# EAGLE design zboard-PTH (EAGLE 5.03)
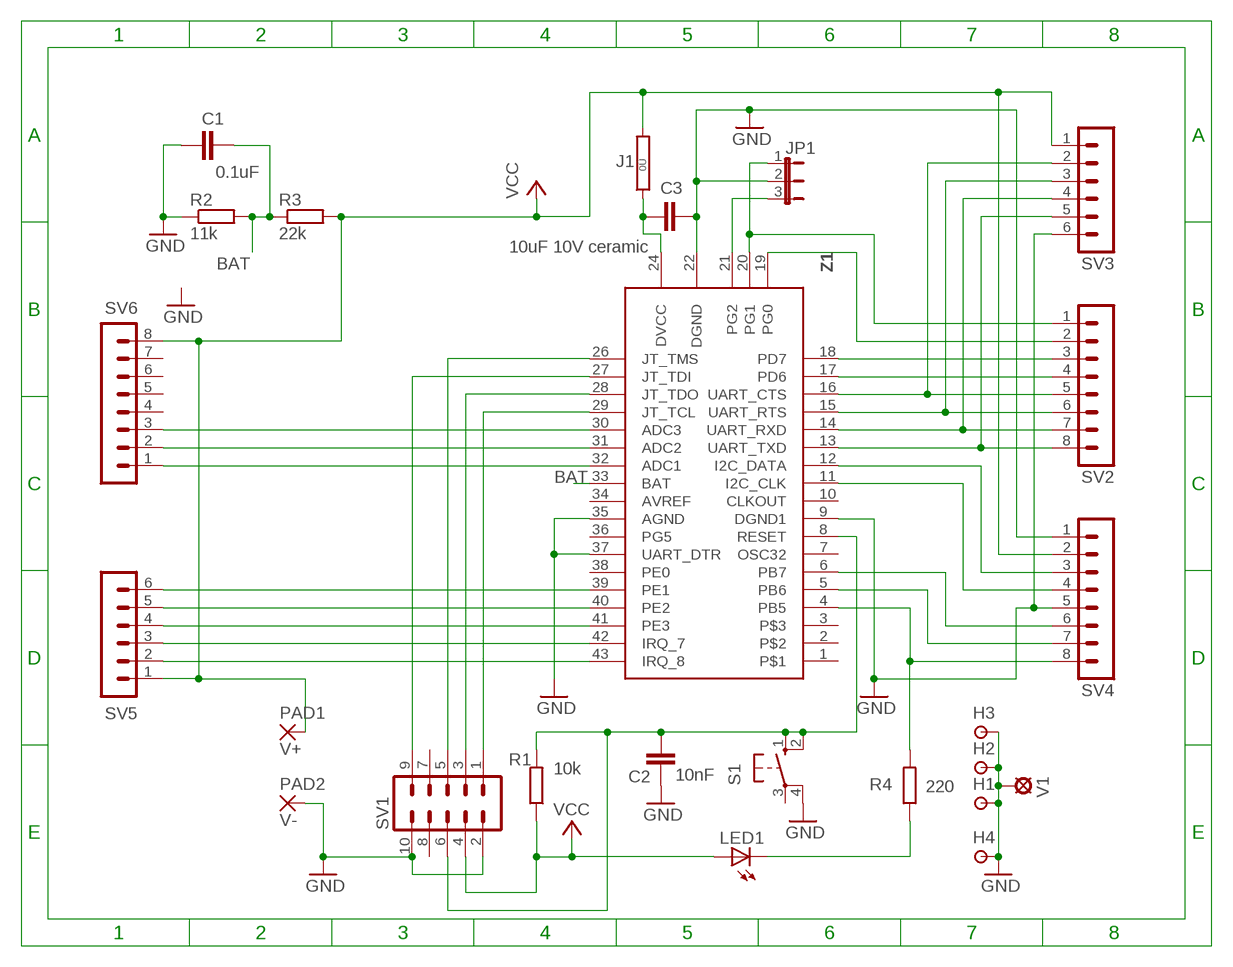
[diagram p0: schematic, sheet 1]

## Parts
C1  0.1uF  C5P  [C050-030-075]
C2  10nF  C5P  [C050-030-075]
C3  10uF 10V ceramic  CSMT0805  [C0805]
H1  HOLE/SMALL  [1,6/0,8]
H2  HOLE/SMALL  [1,6/0,8]
H3  HOLE/SMALL  [1,6/0,8]
H4  HOLE/SMALL  [1,6/0,8]
J1  0R  [0R/10]
JP1  JP2E  [JP2]
LED1  LED-3MM3MM  [HLMP-D105]
PAD1  V+  TERMINAL-PAD  [2,54/1,1]
PAD2  V-  TERMINAL-PAD  [2,54/1,1]
R1  10k  R  [0207/10]
R2  11k  R  [0207/10]
R3  22k  R  [0207/10]
R4  220  R  [0207/10]
S1  10-XX  [B3F-10XX]
SV1  ML10  [ML10]
SV2  MA08-1  [MA08-1]
SV3  MA06-1  [MA06-1]
SV4  MA08-1  [MA08-1]
SV5  MA06-1  [MA06-1]
SV6  MA08-1  [MA08-1]
V1  HOLE/VIA  [LSP10]
Z1  ZDM-A1281-A2N  [ZIGSMD]

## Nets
BAT: C1.2 R2.2 R3.1 Z1.33(BAT)
GND: C1.1 C2.1 C3.2 H1.1(P) H2.1(P) H3.1(P) H4.1(P) JP1.2 PAD2.1(P) R2.1 S1.4(P1) SV1.2 SV1.10 SV3.6 SV4.1 SV4.5 V1.MP Z1.9(DGND1) Z1.22(DGND) Z1.35(AGND) Z1.37(UART_DTR)
N$3: SV6.2 Z1.31(ADC2)
N$4: SV6.3 Z1.30(ADC3)
N$5: SV6.1 Z1.32(ADC1)
N$7: SV5.4 Z1.41(PE3)
N$9: SV1.5 Z1.26(JT_TMS)
N$10: SV1.1 Z1.29(JT_TCL)
N$11: SV1.3 Z1.28(JT_TDO)
N$12: SV5.6 Z1.39(PE1)
N$13: C2.2 R1.2 S1.1(S) S1.2(S1) SV1.6 Z1.8(RESET)
N$14: SV5.3 Z1.42(IRQ_7)
N$15: SV5.2 Z1.43(IRQ_8)
N$16: SV2.3 Z1.18(PD7)
N$17: SV2.4 Z1.17(PD6)
N$18: SV2.5 SV3.2 Z1.16(UART_CTS)
N$19: SV2.6 SV3.3 Z1.15(UART_RTS)
N$20: SV2.7 SV3.4 Z1.14(UART_RXD)
N$21: SV2.8 SV3.5 Z1.13(UART_TXD)
N$22: SV4.3 Z1.12(I2C_DATA)
N$23: SV4.4 Z1.11(I2C_CLK)
N$24: SV2.2 Z1.19(PG0)
N$25: JP1.1 SV2.1 Z1.20(PG1)
N$26: SV4.6 Z1.6(PB7)
N$27: SV4.7 Z1.5(PB6)
N$28: R4.2 SV4.8 Z1.4(PB5)
N$29: JP1.3 Z1.21(PG2)
N$30: LED1.K(C) R4.1
N$31: SV1.9 Z1.27(JT_TDI)
N$32: SV5.5 Z1.40(PE2)
N$33 [supply]: C3.1 J1.1 Z1.24(DVCC)
VCC: J1.2 LED1.A PAD1.1(P) R1.1 R3.2 SV1.4 SV3.1 SV4.2 SV5.1 SV6.8
Unconnected: S1.3(P) SV1.7 SV1.8 SV6.4 SV6.5 SV6.6 SV6.7 Z1.1 Z1.2 Z1.3 Z1.7(OSC32) Z1.10(CLKOUT) Z1.34(AVREF) Z1.36(PG5) Z1.38(PE0)

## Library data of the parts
C1-C3 = ee2parts:C: Capacitor
H1-H4 = ee2parts:HOLE/SMALL: SMALL THROUGH-HOLE PAD/TESTPOINT
J1 = jumper:0R: Bridge 0R 10mm
JP1 = jumper:JP2E: JUMPER
LED1 = ee2parts:LED-3MM: LED
PAD1 PAD2 = ee2parts:TERMINAL-PAD: LARGE THROUGH-HOLE PAD
R1-R4 = ee2parts:R: Resistor
S1 = switch-omron:10-XX: OMRON SWITCH
SV1 = con-harting-ml:ML10: HARTING
SV2 SV4 SV6 = con-lstb:MA08-1: PIN HEADER
SV3 SV5 = con-lstb:MA06-1: PIN HEADER
V1 = ee2parts:HOLE/VIA: FIXED VIA
Z1 = ee2parts:ZDM-A1281-A2

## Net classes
1 supply: width 0.635 mm

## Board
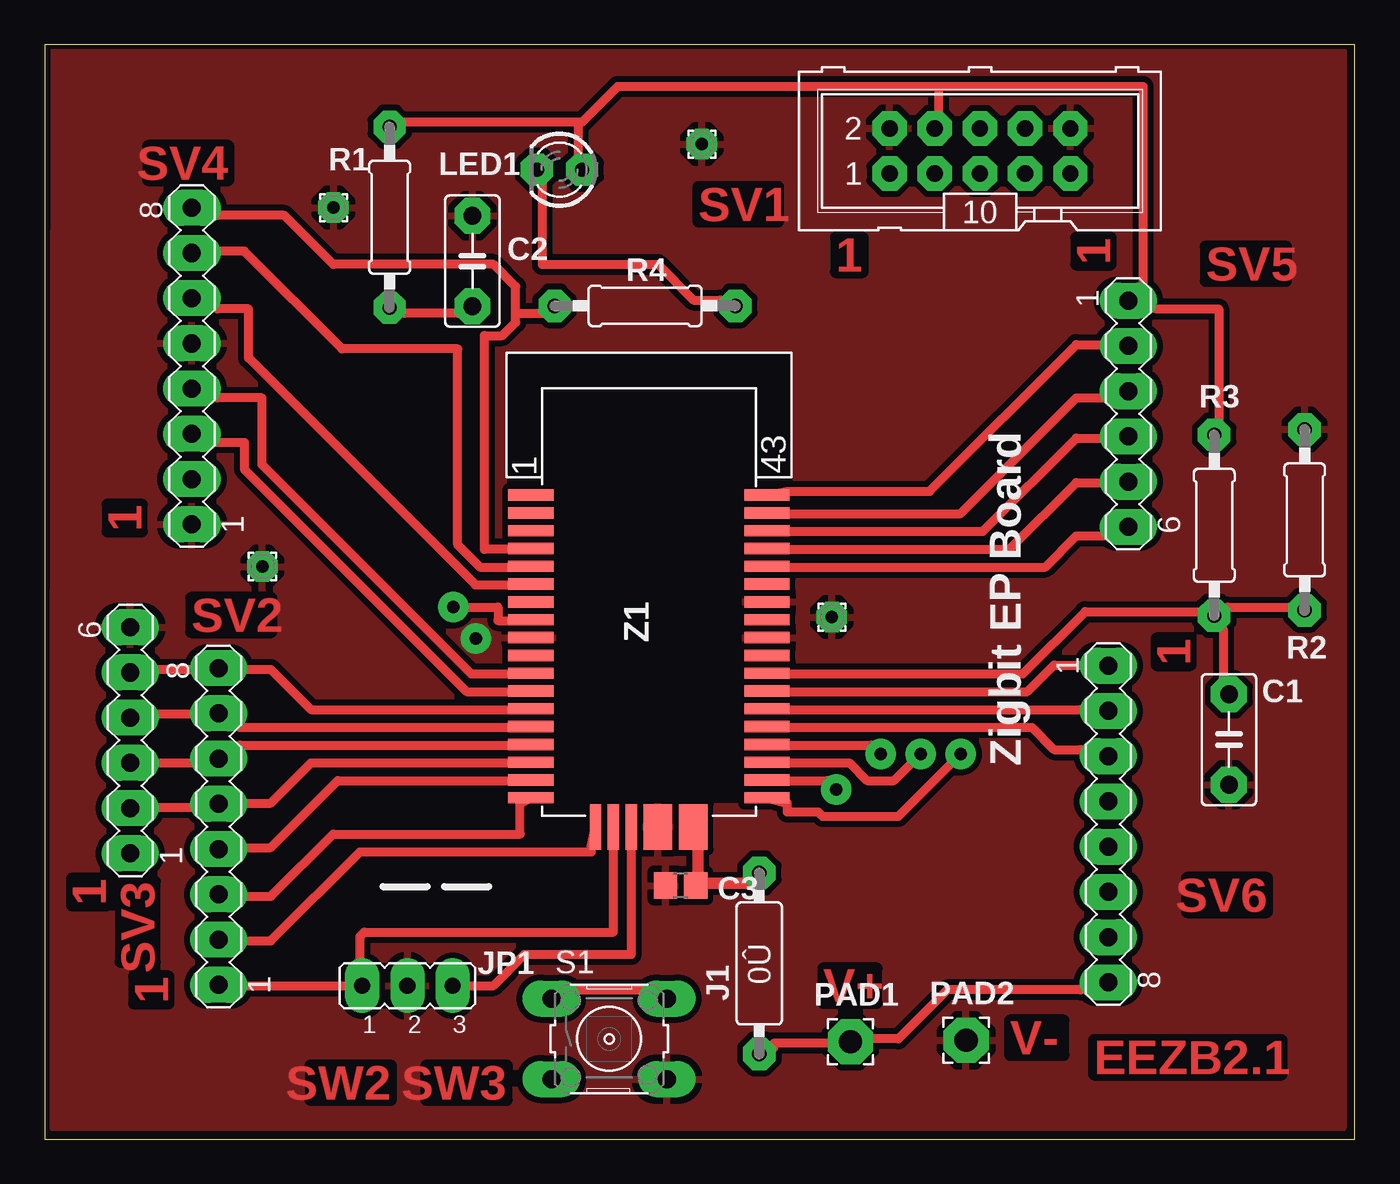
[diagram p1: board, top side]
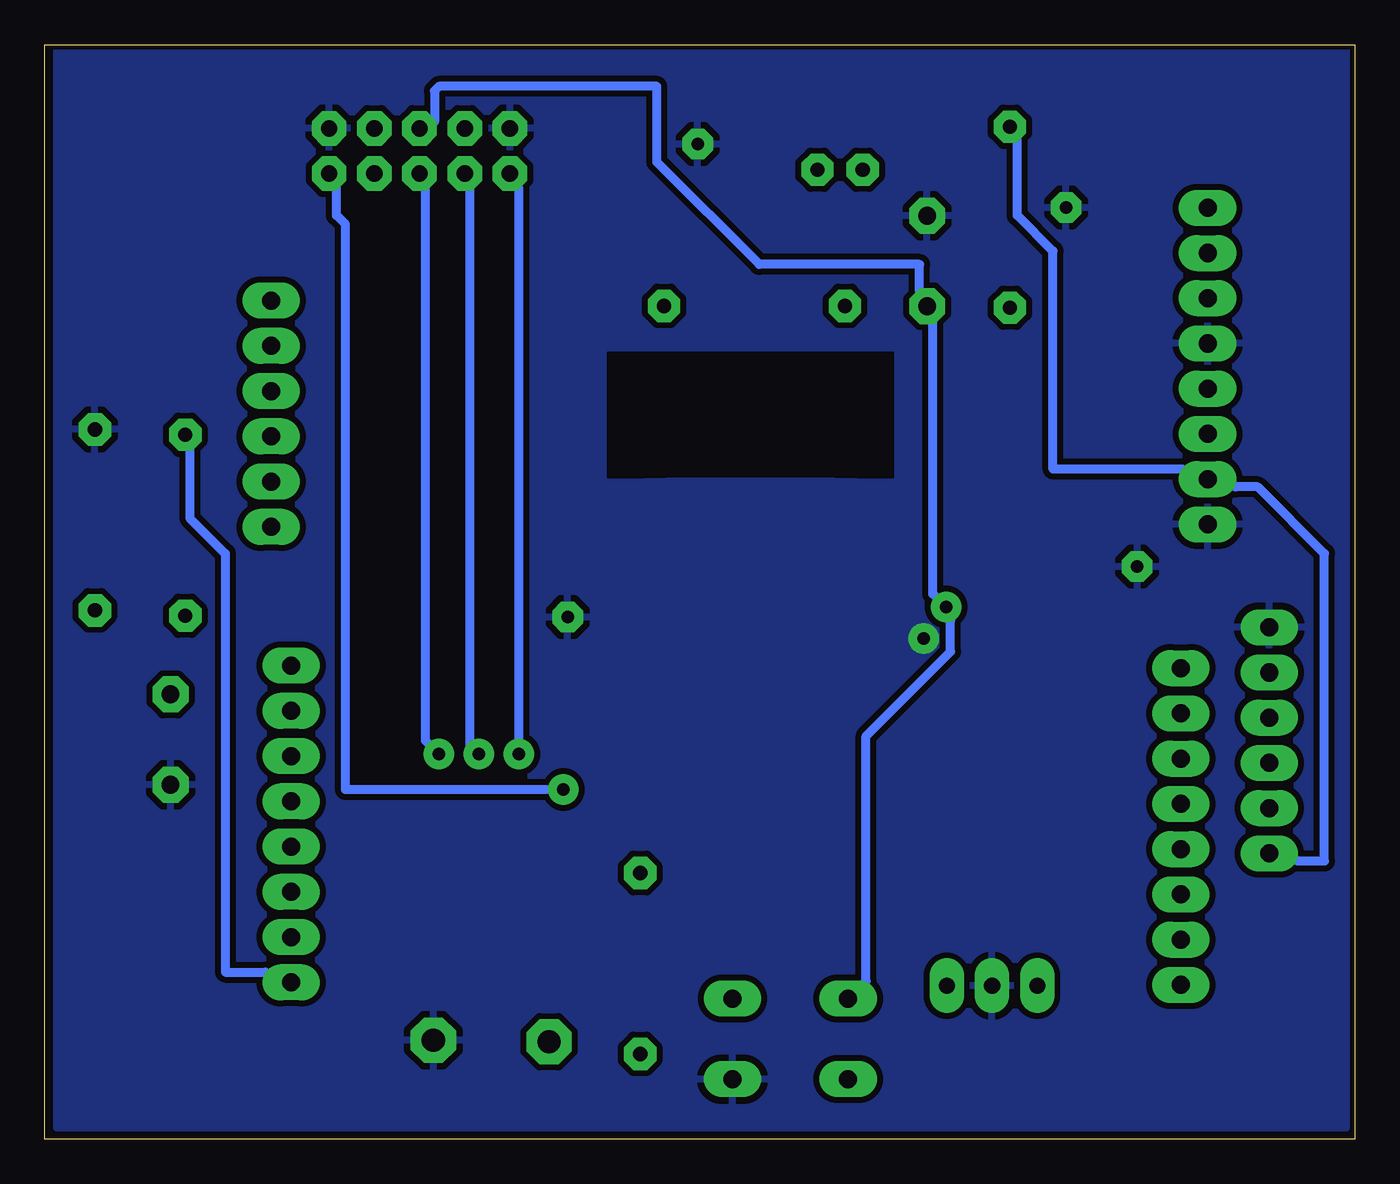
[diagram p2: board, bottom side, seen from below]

Size 73.63 x 61.48 mm. Coordinates in mm from the lower left corner, seen from the top.
Outline: 0,0 73.63,0 73.63,61.48 0,61.48 0,0
Copper layers (1*16): Top 0.035mm / dielectric 1.5mm / Bottom 0.035mm
Design rules "zigbit_rules *": minimum track width 20mil, minimum drill 0.7mm, track to track 13mil, track to pad 13mil, pad to pad 13mil, via to via 13mil, smd to smd 0mil, copper to edge 10mil, drill to drill 10mil, minimum pad ring 20mil, minimum via ring 20mil, stop-mask expansion 0mil, vias tented up to drill 0mil, thermal gap 15mil

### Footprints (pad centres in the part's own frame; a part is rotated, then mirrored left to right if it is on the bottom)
C050-030-075 = drill 1 octagon: 1 -2.54,0; 2 2.54,0
C0805 = smd 1.3 x 1.5: 1 -0.85,0; 2 0.85,0
1,6/0,8 = drill 0.7 pad 1.6 octagon: 1 0,0
0R/10 = drill 0.813 pad 1.6 octagon: 1 -5.08,0; 2 5.08,0
JP2 = drill 0.914 long: 1 -2.54,0; 2 0,0; 3 2.54,0
HLMP-D105 = drill 0.8 octagon: A -1.27,0; K 1.27,0
2,54/1,1 = drill 1.3 pad 2.54 octagon: 1 0,0
0207/10 = drill 0.8 octagon: 1 -5.08,0; 2 5.08,0
B3F-10XX = drill 1.016 long: 1 -3.251,2.261; 2 3.251,2.261; 3 -3.251,-2.261; 4 3.251,-2.261
ML10 = drill 0.914 octagon: 1 -5.08,-1.27; 2 -5.08,1.27; 3 -2.54,-1.27; 4 -2.54,1.27; 5 0,-1.27; 6 0,1.27; 7 2.54,-1.27; 8 2.54,1.27; 9 5.08,-1.27; 10 5.08,1.27
MA08-1 = drill 1.016 long: 1 -8.89,0; 2 -6.35,0; 3 -3.81,0; 4 -1.27,0; 5 1.27,0; 6 3.81,0; 7 6.35,0; 8 8.89,0
MA06-1 = drill 1.016 long: 1 -6.35,0; 2 -3.81,0; 3 -1.27,0; 4 1.27,0; 5 3.81,0; 6 6.35,0
LSP10 = drill 0.7 pad 1.016 round: MP 0,0
ZIGSMD = smd 0.635 x 2.54: 1 7,6.635; 2 6,6.635; 3 5,6.635; 4 4,6.635; 5 3,6.635; 6 2,6.635; 7 1,6.635; 8 0,6.635; 9 -1,6.635; 10 -2,6.635; 11 -3,6.635; 12 -4,6.635; 13 -5,6.635; 14 -6,6.635; 15 -7,6.635; 16 -8,6.635; 17 -9,6.635; 18 -10,6.635; 26 -10,-6.635; 27 -9,-6.635; 28 -8,-6.635; 29 -7,-6.635; 30 -6,-6.635; 31 -5,-6.635; 32 -4,-6.635; 33 -3,-6.635; 34 -2,-6.635; 35 -1,-6.635; 36 0,-6.635; 37 1,-6.635; 38 2,-6.635; 39 3,-6.635; 40 4,-6.635; 41 5,-6.635; 42 6,-6.635; 43 7,-6.635 | smd 2.54 x 0.635: 19 -11.635,3; 20 -11.635,2; 21 -11.635,1 | smd 2.54 x 1.6: 22 -11.635,-0.5; 24 -11.635,-2.5

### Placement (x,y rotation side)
C1  66.55,22.44 90 top
C2  24.04,49.32 270 top
C3  35.74,14.25 180 top
H1  44.24,29.32 0 top
H2  36.94,55.89 0 top
H3  12.24,32.16 0 top
H4  16.24,52.32 0 top
J1  40.16,9.87 270 top
JP1  20.39,8.62 0 top
LED1  28.93,54.45 180 top
PAD1  45.28,5.47 0 top
PAD2  51.78,5.55 0 top
R1  19.39,51.78 270 top
R2  70.8,34.78 270 top
R3  65.72,34.48 90 top
R4  33.74,46.8 180 top
S1  31.73,5.63 0 top
SV1  52.56,55.5 0 top
SV2  9.78,17.56 90 top
SV3  4.82,22.4 90 top
SV4  8.28,43.42 90 top
SV5  60.89,40.74 270 top
SV6  59.77,17.7 270 top
V1  24.24,28.13 0 top
Z1  33.96,29.17 90 top

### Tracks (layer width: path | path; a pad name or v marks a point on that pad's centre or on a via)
BAT
  Top 0.508: Z1.33 41.72,26.13 54.97,26.13 58.47,29.63 64.97,29.63 R3.1 | R2.2 69.97,29.88 66.47,29.88 R3.1 | C1.2 66.22,25.88 66.22,28.63 R3.1
GND
  pour Bottom: 0.47,61.13 72.97,61.13 72.97,0.63 0.47,0.63
  pour Top: 0.53,61.13 72.97,61.13 72.97,0.63 0.47,0.63
N$3
  Top 0.508: Z1.31 41.72,24.13 58.22,24.13 SV6.2
N$4
  Top 0.508: Z1.30 41.72,23.13 55.47,23.13 56.72,21.88 58.22,21.88 SV6.3
N$5
  Top 0.508: Z1.32 41.72,25.13 55.22,25.13 56.72,26.63 58.22,26.63 SV6.1
N$7
  Top 0.508: Z1.41 41.72,34.13 52.72,34.13 57.97,39.38 59.47,39.38 SV5.4
N$9  (via drill 0.7)
  Top 0.508: v51.47,21.63 47.97,18.13 43.72,18.13 43.47,18.38 41.72,18.38 41.72,18.88 Z1.26
  Bottom 0.508: v51.47,21.63 52.22,22.38 52.22,53.38 SV1.5
N$10  (via drill 0.7)
  Top 0.508: v46.97,21.63 46.47,22.13 41.72,22.13 Z1.29
  Bottom 0.508: v46.97,21.63 46.97,53.38 SV1.1
N$11  (via drill 0.7)
  Top 0.508: v49.22,21.63 47.72,20.13 46.22,20.13 45.22,21.13 41.72,21.13 Z1.28
  Bottom 0.508: v49.22,21.63 49.72,22.13 49.72,53.38 SV1.3
N$12
  Top 0.508: Z1.39 41.72,32.13 56.22,32.13 57.97,33.88 59.47,33.88 SV5.6
N$13  (via drill 0.7)
  Top 0.508: S1.1 29.97,8.38 33.47,8.38 S1.2 | v22.97,29.88 25.47,29.88 25.47,29.13 26.22,29.13 Z1.8 | R1.2 20.22,46.38 23.22,46.38 C2.2
  Bottom 0.508: SV1.6 51.72,57.13 51.72,58.88 51.47,59.13 39.22,59.13 39.22,54.88 33.47,49.13 24.47,49.13 24.47,47.63 C2.2 23.72,45.88 23.72,30.63 v22.97,29.88 22.72,29.13 22.72,27.38 27.47,22.63 27.47,8.88 S1.1
N$14
  Top 0.508: Z1.42 41.72,35.13 51.47,35.13 57.97,41.63 59.47,41.63 SV5.3
N$15
  Top 0.508: Z1.43 41.72,36.38 49.72,36.38 57.97,44.63 59.47,44.63 SV5.2
N$16
  Top 0.508: Z1.18 26.72,18.88 26.72,17.13 16.22,17.13 12.72,13.63 11.22,13.63 SV2.3
N$17
  Top 0.508: Z1.17 26.22,20.13 16.47,20.13 12.72,16.38 11.22,16.38 SV2.4
N$18
  Top 0.508: Z1.16 26.22,21.13 14.97,21.13 12.72,18.88 11.22,18.88 SV2.5 8.22,18.63 6.22,18.63 SV3.2
N$19
  Top 0.508: Z1.15 26.22,22.13 10.97,22.13 SV2.6 8.22,21.13 SV3.3
N$20
  Top 0.508: Z1.14 26.22,23.13 10.97,23.13 SV2.7 8.22,23.88 6.22,23.88 SV3.4
N$21
  Top 0.508: Z1.13 26.22,24.13 14.97,24.13 12.72,26.38 11.22,26.38 SV2.8 8.22,26.38 6.22,26.38 SV3.5
N$22
  Top 0.508: Z1.12 26.22,25.13 23.72,25.13 11.22,37.63 11.22,39.13 9.72,39.13 SV4.3
N$23
  Top 0.508: Z1.11 26.22,26.13 23.97,26.13 12.22,37.88 12.22,41.63 9.72,41.63 SV4.4
N$24
  Top 0.508: Z1.19 30.72,16.38 30.72,16.13 17.72,16.13 12.72,11.13 11.22,11.13 SV2.2
N$25
  Top 0.508: Z1.20 31.97,16.38 31.97,11.63 17.97,11.63 17.72,11.38 17.72,10.13 JP1.1 16.97,8.63 11.22,8.63 SV2.1
N$26
  Top 0.508: Z1.6 26.22,31.13 24.22,31.13 11.47,43.88 11.47,46.63 9.72,46.63 SV4.6
N$27
  Top 0.508: Z1.5 26.22,32.13 24.47,32.13 23.22,33.38 23.22,44.38 16.72,44.38 11.22,49.88 9.72,49.88 SV4.7
N$28
  Top 0.508: 26.47,46.38 26.47,45.88 25.72,45.13 24.72,45.13 24.72,33.13 26.22,33.13 Z1.4 | 26.47,46.38 27.97,46.38 R4.2 | SV4.8 9.72,51.88 13.47,51.88 16.22,49.13 25.22,49.13 26.47,47.88 26.47,46.38
N$29
  Top 0.508: Z1.21 32.97,16.38 32.97,10.38 26.97,10.38 25.22,8.63 23.72,8.63 JP1.3
N$30
  Top 0.508: LED1.K 27.97,53.63 27.97,49.13 34.47,49.13 36.47,47.13 37.97,47.13 R4.1
N$31  (via drill 0.7)
  Top 0.508: v44.47,19.63 43.97,20.13 41.72,20.13 Z1.27
  Bottom 0.508: v44.47,19.63 56.72,19.63 56.72,51.38 57.22,51.88 57.22,53.38 SV1.9
N$32
  Top 0.508: Z1.40 41.72,33.13 54.22,33.13 57.97,36.88 59.47,36.88 SV5.5
N$33
  Top 0.635: Z1.24 36.72,16.38 36.72,14.88 C3.1 37.22,14.38 39.47,14.38 J1.1
VCC
  Top 0.508: J1.2 40.97,5.13 40.97,5.38 44.22,5.38 PAD1.1 46.47,5.63 47.97,5.63 50.72,8.38 58.22,8.38 SV6.8 | R3.2 65.97,40.38 65.97,46.63 62.47,46.63 SV5.1 61.72,47.88 61.72,59.13 50.22,59.13 | 29.97,57.13 29.97,55.13 LED1.A | 29.97,57.13 20.22,57.13 R1.1 | 50.22,59.13 50.22,57.63 SV1.4 | 50.22,59.13 32.22,59.13 30.22,57.13 29.97,57.13
  Bottom 0.508: SV3.1 3.22,15.63 1.72,15.63 1.72,32.88 5.47,36.63 6.72,36.63 SV4.2 9.72,37.63 16.97,37.63 16.97,49.88 18.97,51.88 18.97,56.13 R1.1 | SV6.8 61.22,9.38 63.47,9.38 63.47,32.88 65.47,34.88 65.47,38.88 R3.2

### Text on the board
Top: 1 | 1 | 1 | 1 | 1 | 1 | SW2 | SW3 | EEZB2.1
tPlace: Zigbit EP Board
